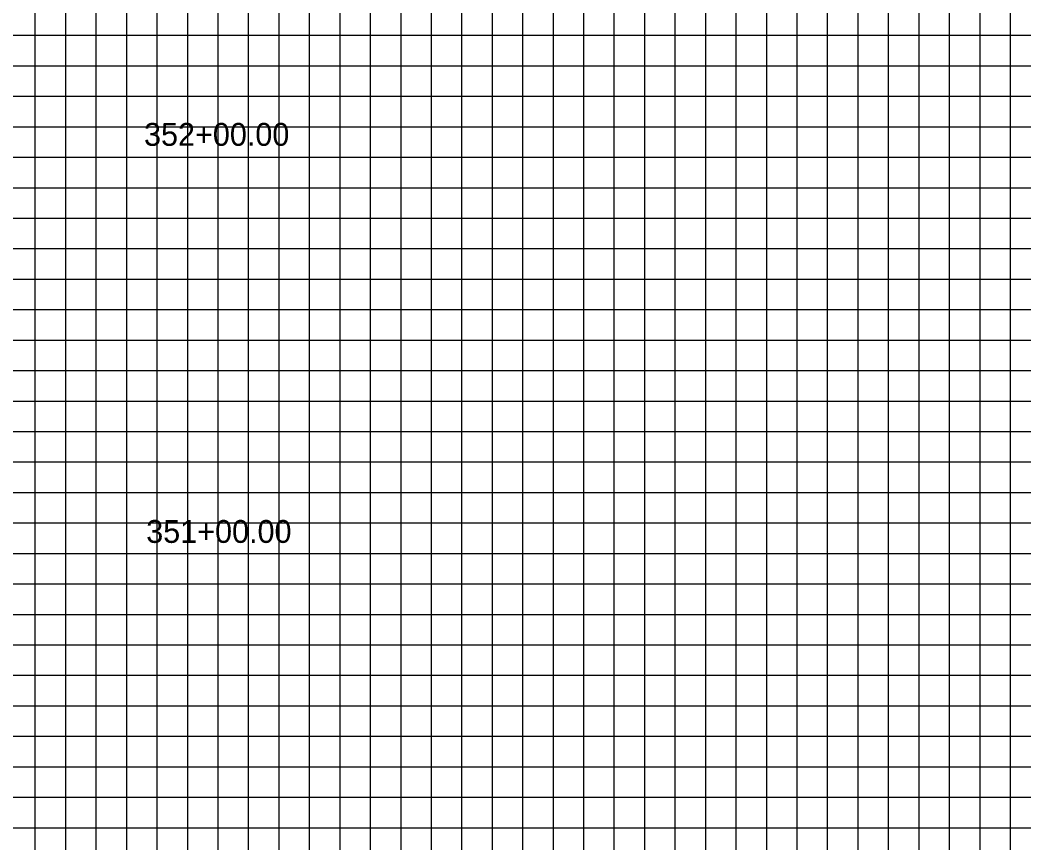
# Model space of a CAD drawing. Extents: x 967 to 1326, y 964 to 1744.
# Drawn here: x 1147 to 1212.9, y 1019 to 1073 of the extents above; entities that cross this region are included whole.
import ezdxf

# ---------------------------------------------------------------- set-up
doc = ezdxf.new("R2010")
doc.units = 0
for name, color, linetype in [('Default', 7, 'Continuous'), ('RD_SHT_MjGrid', 7, 'Continuous'), ('RD_SHT_MnGrid', 7, 'Continuous')]:
    doc.layers.add(name, color=color, linetype=linetype)

msp = doc.modelspace()

# ---------------------------------------------------------------- linework, layer by layer
at = {"layer": 'RD_SHT_MjGrid'}
for p, q in [((1150, 1000), (1150, 1170)), ((1160, 1000), (1160, 1170)), ((1170, 1000), (1170, 1170)), ((1180, 1000), (1180, 1170)), ((1190, 1000), (1190, 1170)), ((1200, 1000), (1200, 1170)), ((1210, 1000), (1210, 1170)), ((1000, 1070), (1320, 1070)), ((1000, 1060), (1320, 1060)), ((1000, 1050), (1320, 1050)), ((1000, 1040), (1320, 1040)), ((1000, 1030), (1320, 1030)), ((1000, 1020), (1320, 1020))]:
    msp.add_line(p, q, dxfattribs=at)
at = {"layer": 'RD_SHT_MnGrid'}
for p, q in [((1148, 1000), (1148, 1170)), ((1152, 1000), (1152, 1170)), ((1154, 1000), (1154, 1170)), ((1156, 1000), (1156, 1170)), ((1158, 1000), (1158, 1170)), ((1162, 1000), (1162, 1170)), ((1164, 1000), (1164, 1170)), ((1166, 1000), (1166, 1170)), ((1168, 1000), (1168, 1170)), ((1172, 1000), (1172, 1170)), ((1174, 1000), (1174, 1170)), ((1176, 1000), (1176, 1170)), ((1178, 1000), (1178, 1170)), ((1182, 1000), (1182, 1170)), ((1184, 1000), (1184, 1170)), ((1186, 1000), (1186, 1170)), ((1188, 1000), (1188, 1170)), ((1192, 1000), (1192, 1170)), ((1194, 1000), (1194, 1170)), ((1196, 1000), (1196, 1170)), ((1198, 1000), (1198, 1170)), ((1202, 1000), (1202, 1170)), ((1204, 1000), (1204, 1170)), ((1206, 1000), (1206, 1170)), ((1208, 1000), (1208, 1170)), ((1212, 1000), (1212, 1170)), ((1000, 1072), (1320, 1072)), ((1000, 1068), (1320, 1068)), ((1000, 1066), (1320, 1066)), ((1000, 1064), (1320, 1064)), ((1000, 1062), (1320, 1062)), ((1000, 1058), (1320, 1058)), ((1000, 1056), (1320, 1056)), ((1000, 1054), (1320, 1054)), ((1000, 1052), (1320, 1052)), ((1000, 1048), (1320, 1048)), ((1000, 1046), (1320, 1046)), ((1000, 1044), (1320, 1044)), ((1000, 1042), (1320, 1042)), ((1000, 1038), (1320, 1038)), ((1000, 1036), (1320, 1036)), ((1000, 1034), (1320, 1034)), ((1000, 1032), (1320, 1032)), ((1000, 1028), (1320, 1028)), ((1000, 1026), (1320, 1026)), ((1000, 1024), (1320, 1024)), ((1000, 1022), (1320, 1022))]:
    msp.add_line(p, q, dxfattribs=at)

# ---------------------------------------------------------------- texts
at = {"layer": 'Default'}
for s, p in [('352+00.00', (1155.134, 1064.748)), ('351+00.00', (1155.278, 1038.691))]:
    msp.add_text(s, height=1.5, dxfattribs=at).set_placement(p)

doc.saveas('drawing.dxf')
